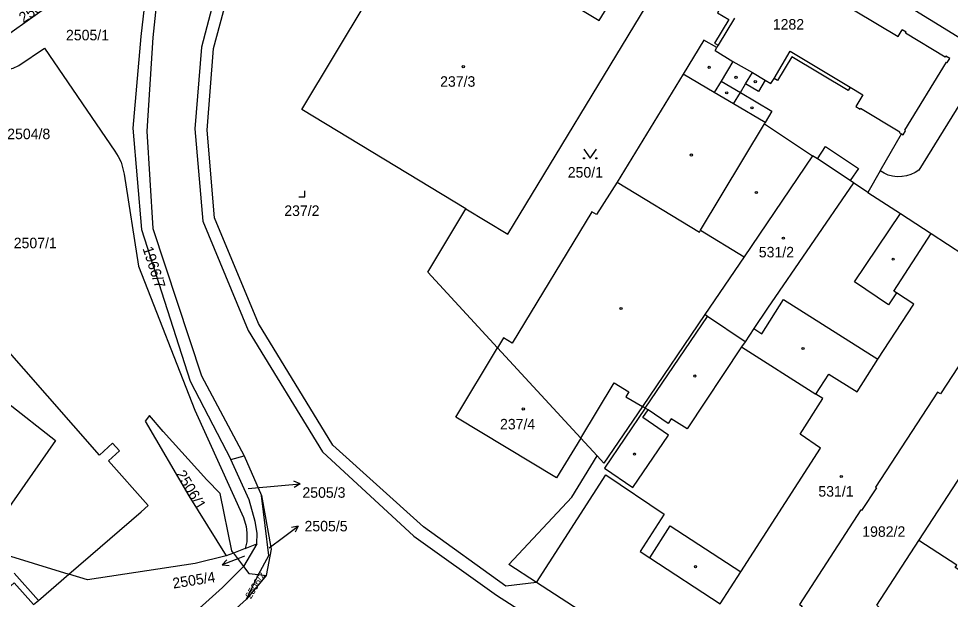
# Model space of a CAD drawing. Extents: x -679220 to -673243, y -1075091 to -1066557.
# Drawn here: x -676221 to -676070.5, y -1071960.5 to -1071866.6 of the extents above; entities that cross this region are included whole.
import ezdxf

# ---------------------------------------------------------------- set-up
doc = ezdxf.new("R2010")
doc.units = 0
for name, color, linetype in [('Hranice parcel', 7, 'Continuous'), ('Parcelní čísla', 7, 'Continuous'), ('Pop  PČ popisy', 7, 'Continuous'), ('Vnitřní kresba', 7, 'Continuous'), ('Značky budov', 7, 'Continuous'), ('Značky kultur', 7, 'Continuous')]:
    doc.layers.add(name, color=color, linetype=linetype)

msp = doc.modelspace()

# ---------------------------------------------------------------- linework, layer by layer
at = {"layer": 'Hranice parcel'}
for p, q in [((-676064.23, -1071872.66), (-676075.57, -1071891.12)), ((-676081.85, -1071891.26), (-676083.84, -1071894.72)), ((-676083.84, -1071894.72), (-676086.16, -1071893.16)), ((-676130.19, -1071934.42), (-676143.64, -1071919.82)), ((-676127.54, -1071937.3), (-676130.19, -1071934.42)), ((-676186.7, -1071937.9), (-676184.56, -1071937.27)), ((-676184.56, -1071937.27), (-676181.72, -1071943.69)), ((-676182.49, -1071951.53), (-676184.63, -1071955.2)), ((-676184.39, -1071952.29), (-676182.49, -1071951.53)), ((-676227.09, -1071952.06), (-676212.87, -1071956.4)), ((-676186.26, -1071953.03), (-676187.44, -1071953.46)), ((-676184.39, -1071952.29), (-676186.26, -1071953.03)), ((-676186.26, -1071953.03), (-676184.63, -1071955.2)), ((-676184.17, -1071960.43), (-676182.21, -1071956.47)), ((-676180.99, -1071956.61), (-676184.17, -1071960.43)), ((-676182.21, -1071956.47), (-676180.99, -1071956.61)), ((-676184.17, -1071960.43), (-676195.03, -1071970.17))]:
    msp.add_line(p, q, dxfattribs=at)
for points in [[(-676099.38, -1071590.43), (-676125.1, -1071603.36), (-676134.03, -1071611.63), (-676132.28, -1071638.9), (-676113.31, -1071708.7), (-676111.17, -1071722.51), (-676112.16, -1071739.84), (-676114.63, -1071749.43), (-676121.41, -1071764.03), (-676135.15, -1071783.33), (-676142.46, -1071792.76), (-676166.36, -1071822.04), (-676175.39, -1071833.12), (-676182.45, -1071844.4), (-676187.2, -1071855.01), (-676191.45, -1071871.27), (-676192.51, -1071884.43), (-676191.2, -1071899.37), (-676183.88, -1071917.06), (-676171.89, -1071936.65), (-676157.14, -1071950.29), (-676143.77, -1071959.8), (-676108.24, -1071982.64), (-676103.47, -1071979.82)], [(-676137.35, -1071957.74), (-676142.3, -1071958.36), (-676155.61, -1071948.79), (-676170.23, -1071935.55), (-676182.22, -1071915.93), (-676189.31, -1071898.82), (-676190.52, -1071884.65), (-676189.49, -1071871.47), (-676185.21, -1071855.48), (-676180.3, -1071844.64), (-676174.29, -1071835.37), (-676172.03, -1071834.46)], [(-676108.73, -1071845.19), (-676096.94, -1071852.46), (-676087.97, -1071858.01), (-676064.23, -1071872.66)], [(-676148.73, -1071897.4), (-676175.24, -1071881.3), (-676164.68, -1071863.76), (-676156.2, -1071849.56), (-676127.2, -1071866.96), (-676125.25, -1071863.71)], [(-676206.65, -1071856.66), (-676214.57, -1071863.42), (-676227.08, -1071872.34)], [(-676200.03, -1071859.2), (-676201.25, -1071869.53), (-676202.55, -1071884.32), (-676201.11, -1071900.72), (-676193.28, -1071925.25), (-676186.7, -1071937.9)], [(-676148.73, -1071897.4), (-676141.99, -1071901.49), (-676119.61, -1071864.62), (-676120.07, -1071864.12), (-676117.2, -1071859.34)], [(-676117.2, -1071859.34), (-676107.76, -1071865.12), (-676108.1, -1071865.68), (-676106.29, -1071866.79), (-676108.57, -1071870.6), (-676108.01, -1071870.94), (-676108.21, -1071871.29), (-676110.3, -1071870.13), (-676113.64, -1071875.61), (-676124.3, -1071893.09), (-676127.65, -1071898.27), (-676128.38, -1071897.84), (-676141.28, -1071919.09), (-676142.69, -1071918.24), (-676143.64, -1071919.82)], [(-676198.56, -1071862.46), (-676199.27, -1071869.68), (-676200.26, -1071884.85), (-676199.27, -1071900.55), (-676191.45, -1071924.38), (-676184.56, -1071937.27)], [(-676227.08, -1071872.34), (-676226.86, -1071873.32), (-676225.29, -1071874.56), (-676224.35, -1071874.89), (-676222.83, -1071874.93), (-676221.84, -1071874.67), (-676220.94, -1071874.24), (-676216.81, -1071871.39), (-676205.41, -1071888.05), (-676204.87, -1071888.91), (-676204.42, -1071889.82), (-676203.93, -1071891.77), (-676201.63, -1071906.65), (-676192.52, -1071929.9), (-676184.66, -1071947.23), (-676184.22, -1071948.69), (-676184.11, -1071949.73), (-676184.14, -1071951.2), (-676184.39, -1071952.29)], [(-676086.16, -1071893.16), (-676086.67, -1071892.82), (-676091.98, -1071889.3), (-676092.75, -1071888.79), (-676103.81, -1071905.11), (-676110.15, -1071914.47), (-676120.2, -1071929.3)], [(-676075.57, -1071891.12), (-676076.19, -1071891.52), (-676076.86, -1071891.83), (-676077.56, -1071892.05), (-676078.29, -1071892.17), (-676078.35, -1071892.17), (-676079.09, -1071892.18), (-676079.82, -1071892.1), (-676080.53, -1071891.91), (-676081.21, -1071891.63), (-676081.85, -1071891.26)], [(-676086.16, -1071893.16), (-676100.04, -1071913.43), (-676102.24, -1071916.72), (-676103.66, -1071918.86), (-676104.22, -1071919.7), (-676113.01, -1071932.94), (-676115.57, -1071931.31), (-676116.08, -1071932.09), (-676119.3, -1071929.88), (-676119.79, -1071929.58), (-676120.2, -1071929.3)], [(-676083.84, -1071894.72), (-676078.58, -1071898.15), (-676073.59, -1071901.34), (-676068.34, -1071904.79)], [(-676143.64, -1071919.82), (-676154.88, -1071907.6), (-676148.73, -1071897.4)], [(-676212.87, -1071956.4), (-676201.2, -1071946.34), (-676200.07, -1071945.3), (-676206.47, -1071938.1), (-676204.7, -1071936.5), (-676205.81, -1071935.25), (-676207.9, -1071937.16), (-676228.58, -1071913.66), (-676225.33, -1071910.89), (-676233.96, -1071901.19), (-676236.8, -1071903.68), (-676241.2, -1071898.74), (-676242.19, -1071899.63), (-676258.77, -1071914.06)], [(-676060.69, -1071909.82), (-676072.12, -1071927.28), (-676072.56, -1071926.99), (-676082.57, -1071942.38), (-676082.45, -1071942.45), (-676084.83, -1071946.11), (-676084.95, -1071946.03), (-676094.87, -1071961.29), (-676094.43, -1071961.58), (-676105.42, -1071978.58)], [(-676130.19, -1071934.42), (-676134.09, -1071940.87), (-676150.38, -1071931.03), (-676143.64, -1071919.82)], [(-676222.83, -1071928.67), (-676214.99, -1071934.79), (-676227.09, -1071952.06)], [(-676120.2, -1071929.3), (-676126.44, -1071938.5), (-676127.54, -1071937.3)], [(-676186.26, -1071953.03), (-676186.53, -1071952.67), (-676188.41, -1071943.4), (-676190.56, -1071941.18), (-676197.63, -1071933.34), (-676199.86, -1071930.77), (-676200.53, -1071931.71), (-676193.49, -1071943.78), (-676187.44, -1071953.46)], [(-676182.49, -1071951.53), (-676182.43, -1071949.77), (-676182.78, -1071947.92), (-676183.73, -1071944.39), (-676186.7, -1071937.9)], [(-676137.35, -1071957.74), (-676141.82, -1071954.83), (-676131.61, -1071943.99), (-676127.54, -1071937.3)], [(-676075.57, -1071950.97), (-676069.33, -1071941.38), (-676067.39, -1071938.4)], [(-676182.21, -1071956.47), (-676180.56, -1071953.4), (-676181.72, -1071943.69)], [(-676181.72, -1071943.69), (-676180.21, -1071952.35), (-676180.99, -1071956.61)], [(-676053.8, -1071947.23), (-676055.77, -1071950.27), (-676061.98, -1071959.83), (-676067.63, -1071956.15), (-676067.87, -1071956.53), (-676069.71, -1071955.33), (-676069.47, -1071954.95), (-676075.57, -1071950.97)], [(-676092.58, -1071986.74), (-676075.12, -1071968.28), (-676076.8, -1071966.69), (-676076.9, -1071966.8), (-676080.79, -1071963.11), (-676080.69, -1071963), (-676082.37, -1071961.41), (-676075.57, -1071950.97)], [(-676187.44, -1071953.46), (-676192.44, -1071954.68), (-676209.85, -1071957.32), (-676212.87, -1071956.4)], [(-676224.78, -1071960.53), (-676221.69, -1071957.8), (-676218.56, -1071961.34), (-676217.78, -1071960.65), (-676212.87, -1071956.4)], [(-676184.63, -1071955.2), (-676188.02, -1071958.58), (-676200.85, -1071970.07)], [(-676184.63, -1071955.2), (-676183.8, -1071956.3), (-676182.21, -1071956.47)], [(-676105.42, -1071978.58), (-676114.27, -1071972.74), (-676115.48, -1071974.61), (-676129.77, -1071965.35), (-676128.47, -1071963.53), (-676137.35, -1071957.74)]]:
    msp.add_lwpolyline(points, dxfattribs=at)
at = {"layer": 'Pop  PČ popisy'}
for p, q in [((-676183.91, -1071942.57), (-676178.5, -1071942.07)), ((-676178.5, -1071942.07), (-676175.51, -1071941.81)), ((-676175.51, -1071941.81), (-676176.55, -1071941.4)), ((-676175.51, -1071941.81), (-676176.46, -1071942.4)), ((-676178.2, -1071950.45), (-676175.8, -1071948.64)), ((-676175.8, -1071948.64), (-676176.9, -1071948.85)), ((-676175.8, -1071948.64), (-676176.3, -1071949.65)), ((-676180.49, -1071952.17), (-676178.2, -1071950.45)), ((-676185.32, -1071953.81), (-676188.1, -1071954.93)), ((-676188.1, -1071954.93), (-676187.36, -1071954.09)), ((-676184.51, -1071953.49), (-676185.32, -1071953.81)), ((-676188.1, -1071954.93), (-676186.99, -1071955.02))]:
    msp.add_line(p, q, dxfattribs=at)
at = {"layer": 'Vnitřní kresba'}
for p, q in [((-676090.62, -1071862.5), (-676078.93, -1071869.54)), ((-676105.38, -1071866.57), (-676108.01, -1071870.94)), ((-676078.93, -1071869.54), (-676078.29, -1071868.46)), ((-676077.65, -1071868.85), (-676078.29, -1071868.46)), ((-676077.74, -1071868.99), (-676077.65, -1071868.85)), ((-676071.34, -1071872.86), (-676077.74, -1071868.99)), ((-676108.51, -1071871.77), (-676108.21, -1071871.29)), ((-676108.51, -1071871.77), (-676105.62, -1071873.55)), ((-676098.97, -1071876.29), (-676096.35, -1071871.92)), ((-676096.35, -1071871.92), (-676086.68, -1071877.72)), ((-676105.62, -1071873.55), (-676107.52, -1071876.74)), ((-676105.62, -1071873.55), (-676102.46, -1071875.34)), ((-676096.12, -1071872.79), (-676098.42, -1071876.62)), ((-676087.01, -1071878.27), (-676096.12, -1071872.79)), ((-676077.85, -1071884.69), (-676071.13, -1071873.66)), ((-676071.26, -1071872.71), (-676071.34, -1071872.86)), ((-676070.61, -1071873.1), (-676071.26, -1071872.71)), ((-676071.13, -1071873.66), (-676071, -1071873.74)), ((-676071, -1071873.74), (-676070.61, -1071873.1)), ((-676108.64, -1071878.6), (-676113.64, -1071875.61)), ((-676103.57, -1071877.18), (-676102.46, -1071875.34)), ((-676102.46, -1071875.34), (-676100.39, -1071876.58)), ((-676100.39, -1071876.58), (-676101.48, -1071878.39)), ((-676100.39, -1071876.58), (-676099.48, -1071877.13)), ((-676099.48, -1071877.13), (-676098.97, -1071876.29)), ((-676098.42, -1071876.62), (-676098.97, -1071876.29)), ((-676107.52, -1071876.74), (-676108.64, -1071878.6)), ((-676107.52, -1071876.74), (-676104.41, -1071878.58)), ((-676104.41, -1071878.58), (-676103.57, -1071877.18)), ((-676101.48, -1071878.39), (-676103.57, -1071877.18)), ((-676086.68, -1071877.72), (-676087.01, -1071878.27)), ((-676086.68, -1071877.72), (-676084.63, -1071878.96)), ((-676105.5, -1071880.4), (-676108.64, -1071878.6)), ((-676105.5, -1071880.4), (-676104.41, -1071878.58)), ((-676104.41, -1071878.58), (-676099.31, -1071881.61)), ((-676084.63, -1071878.96), (-676085.76, -1071880.85)), ((-676100.42, -1071883.45), (-676105.5, -1071880.4)), ((-676085.76, -1071880.85), (-676085.09, -1071881.25)), ((-676085.09, -1071881.25), (-676085.01, -1071881.12)), ((-676085.01, -1071881.12), (-676078.68, -1071884.93)), ((-676099.31, -1071881.61), (-676100.42, -1071883.45)), ((-676110.86, -1071900.84), (-676100.53, -1071883.65)), ((-676100.42, -1071883.45), (-676100.53, -1071883.65)), ((-676100.53, -1071883.65), (-676092.75, -1071888.79)), ((-676081.85, -1071891.26), (-676078.39, -1071885.28)), ((-676078.68, -1071884.93), (-676078.76, -1071885.05)), ((-676078.76, -1071885.05), (-676078.39, -1071885.28)), ((-676078.39, -1071885.28), (-676078.13, -1071885.43)), ((-676078.13, -1071885.43), (-676077.72, -1071884.76)), ((-676077.72, -1071884.76), (-676077.85, -1071884.69)), ((-676091.98, -1071889.3), (-676090.64, -1071887.3)), ((-676090.64, -1071887.3), (-676085.34, -1071890.84)), ((-676085.34, -1071890.84), (-676086.67, -1071892.82)), ((-676124.3, -1071893.09), (-676111.04, -1071901.13)), ((-676085.98, -1071909.17), (-676078.58, -1071898.15)), ((-676111.04, -1071901.13), (-676110.86, -1071900.84)), ((-676110.86, -1071900.84), (-676103.81, -1071905.11)), ((-676079.65, -1071910.67), (-676073.59, -1071901.34)), ((-676080.47, -1071912.87), (-676085.98, -1071909.17)), ((-676079.19, -1071910.97), (-676080.47, -1071912.87)), ((-676079.19, -1071910.97), (-676079.65, -1071910.67)), ((-676076.42, -1071912.76), (-676079.19, -1071910.97)), ((-676100.97, -1071917.56), (-676097.46, -1071912.02)), ((-676097.46, -1071912.02), (-676082.19, -1071921.69)), ((-676082.19, -1071921.69), (-676076.42, -1071912.76)), ((-676119.79, -1071929.58), (-676109.74, -1071914.75)), ((-676109.74, -1071914.75), (-676110.15, -1071914.47)), ((-676103.66, -1071918.86), (-676109.74, -1071914.75)), ((-676102.24, -1071916.72), (-676100.97, -1071917.56)), ((-676104.22, -1071919.7), (-676092.23, -1071927.3)), ((-676085.57, -1071926.93), (-676082.19, -1071921.69)), ((-676092.23, -1071927.3), (-676090.11, -1071924.09)), ((-676090.11, -1071924.09), (-676085.57, -1071926.93)), ((-676130.19, -1071934.42), (-676124.82, -1071925.52)), ((-676124.82, -1071925.52), (-676122.42, -1071926.97)), ((-676122.42, -1071926.97), (-676122.91, -1071927.78)), ((-676122.91, -1071927.78), (-676120.2, -1071929.3)), ((-676091.08, -1071928.05), (-676092.23, -1071927.3)), ((-676094.77, -1071933.81), (-676091.08, -1071928.05)), ((-676119.79, -1071929.58), (-676126.35, -1071939.27)), ((-676120.15, -1071931.12), (-676119.3, -1071929.88)), ((-676116.02, -1071933.96), (-676120.15, -1071931.12)), ((-676091.48, -1071936.03), (-676094.77, -1071933.81)), ((-676121.8, -1071942.39), (-676116.02, -1071933.96)), ((-676104.36, -1071956.03), (-676091.48, -1071936.03)), ((-676126.35, -1071939.27), (-676121.8, -1071942.39)), ((-676137.35, -1071957.74), (-676126.13, -1071940.38)), ((-676126.13, -1071940.38), (-676116.72, -1071946.71)), ((-676116.72, -1071946.71), (-676120.62, -1071952.77)), ((-676119.05, -1071953.8), (-676115.77, -1071948.61)), ((-676115.77, -1071948.61), (-676104.36, -1071956.03)), ((-676120.62, -1071952.77), (-676119.05, -1071953.8)), ((-676119.05, -1071953.8), (-676107.69, -1071961.21)), ((-676217.78, -1071960.65), (-676221.69, -1071956.23)), ((-676107.69, -1071961.21), (-676104.36, -1071956.03))]:
    msp.add_line(p, q, dxfattribs=at)
at = {"layer": 'Značky budov'}
for centre in [(-676149.16, -1071874.41), (-676109.45, -1071874.5), (-676105.11, -1071876.13), (-676102.01, -1071876.82), (-676106.62, -1071878.64), (-676102.54, -1071881.06), (-676112.32, -1071888.68), (-676101.83, -1071894.73), (-676097.47, -1071902.11), (-676079.73, -1071905.5), (-676123.69, -1071913.48), (-676094.29, -1071919.94), (-676111.77, -1071924.4), (-676139.47, -1071929.72), (-676121.51, -1071937.01), (-676088.12, -1071940.64), (-676111.65, -1071955.2)]:
    msp.add_circle(centre, 0.175, dxfattribs=at)
at = {"layer": 'Značky kultur'}
for p, q in [((-676174.74, -1071895.45), (-676174.74, -1071894.45)), ((-676175.74, -1071895.45), (-676174.74, -1071895.45))]:
    msp.add_line(p, q, dxfattribs=at)
msp.add_lwpolyline([(-676129.67, -1071887.71), (-676128.67, -1071889.21), (-676127.67, -1071887.71)], dxfattribs=at)
for centre in [(-676129.67, -1071889.21), (-676127.67, -1071889.21)]:
    msp.add_circle(centre, 0.1, dxfattribs=at)

# ---------------------------------------------------------------- texts
at = {"layer": 'Parcelní čísla'}
for s, height, rotation, p in [('2505/2', 1.7, 34, (-676220.2, -1071867.41)), ('1966/7', 1.7, 288, (-676200.97, -1071903.77)), ('2506/1', 1.7, 301, (-676195.63, -1071940.23)), ('2505/4', 1.7, 9, (-676195.97, -1071958.75)), ('2506/2', 1.14, 59, (-676183.47, -1071960.51))]:
    msp.add_text(s, height=height, rotation=rotation, dxfattribs=at).set_placement(p)
for s, p in [('1282', (-676099.18, -1071868.41)), ('2505/1', (-676213.32, -1071870.15)), ('237/3', (-676152.9, -1071877.65)), ('2504/8', (-676222.81, -1071886.12)), ('250/1', (-676132.29, -1071892.33)), ('237/2', (-676178.07, -1071898.53)), ('2507/1', (-676221.76, -1071903.75)), ('531/2', (-676101.44, -1071905.22)), ('237/4', (-676143.23, -1071933.02)), ('2505/3', (-676175.14, -1071944.07)), ('531/1', (-676091.82, -1071943.88)), ('2505/5', (-676174.8, -1071949.5)), ('1982/2', (-676084.73, -1071950.38))]:
    msp.add_text(s, height=1.7, dxfattribs=at).set_placement(p)

doc.saveas('drawing.dxf')
